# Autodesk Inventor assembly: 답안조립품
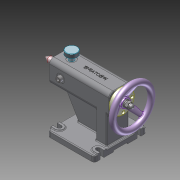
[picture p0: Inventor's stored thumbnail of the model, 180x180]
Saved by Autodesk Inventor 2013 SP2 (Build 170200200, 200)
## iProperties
Created: 2024-07
Part Number: 답안조립품
Document SubType Name: Assembly
Designer: a
Author: a
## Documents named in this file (15)
- C:\Users\a\Desktop\740704V1011\답안조립품.iam
- C:\Users\a\Desktop\740704V1011\본체.ipt
- C:\Users\a\Desktop\740704V1011\나사축.ipt
- C:\Users\a\Desktop\740704V1011\부시.ipt
- C:\Users\a\Desktop\740704V1011\센터.ipt
- C:\Users\a\Desktop\740704V1011\스러스트 볼 베어링 51101.ipt
- C:\Users\a\Desktop\740704V1011\스톱퍼.ipt
- C:\Users\a\Desktop\740704V1011\스프링  와셔 M12.ipt
- C:\Users\a\Desktop\740704V1011\슬리브.ipt
- C:\Users\a\Desktop\740704V1011\육각 소켓 머리 볼트 M6x12.ipt
- C:\Users\a\Desktop\740704V1011\육각 소켓 머리 볼트 M12x16.ipt
- C:\Users\a\Desktop\740704V1011\캡너트 M12.ipt
- C:\Users\a\Desktop\740704V1011\평와셔 M12.ipt
- C:\Users\a\Desktop\740704V1011\평행키 4x4x14.ipt
- C:\Users\a\Desktop\740704V1011\핸들.ipt
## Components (1 placed, 1 different names)
1. 핸들:1
